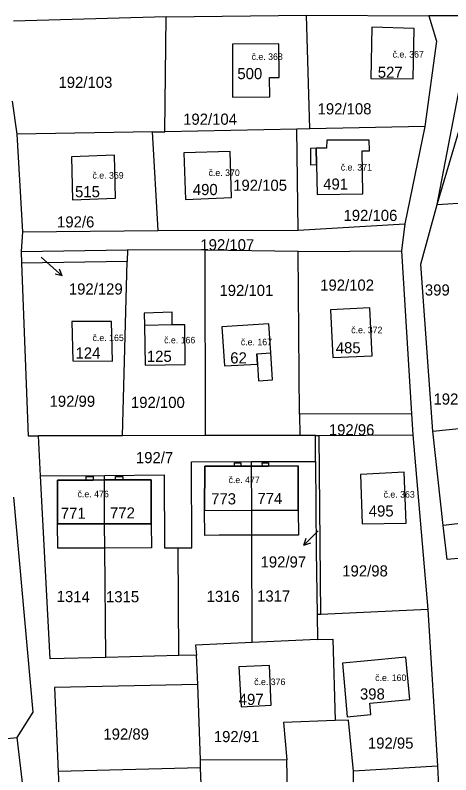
# Model space of a CAD drawing. Extents: x -887272 to -880188, y -1026687 to -1021896.
# Drawn here: x -882399.7 to -882333.3, y -1024170.3 to -1024054.5 of the extents above; entities that cross this region are included whole.
import ezdxf

# ---------------------------------------------------------------- set-up
doc = ezdxf.new("R2010")
doc.units = 0
for name, color, linetype in [('Definiční body', 7, 'Continuous'), ('Hranice parcel', 7, 'Continuous'), ('Parcelní čísla', 7, 'Continuous'), ('Polygon budovy', 7, 'Continuous'), ('Pop  PČ popisy', 7, 'Continuous'), ('Vnitřní kresba', 7, 'Continuous')]:
    doc.layers.add(name, color=color, linetype=linetype)

msp = doc.modelspace()

# ---------------------------------------------------------------- linework, layer by layer
at = {"layer": 'Hranice parcel'}
for p, q in [((-882376.66, -1024054.74), (-882399.93, -1024055.4)), ((-882376.88, -1024072.24), (-882376.66, -1024054.74)), ((-882376.66, -1024054.74), (-882355.26, -1024054.47)), ((-882355.26, -1024054.47), (-882336.63, -1024054.59)), ((-882354.76, -1024071.81), (-882355.26, -1024054.47)), ((-882330.93, -1024054.59), (-882336.63, -1024054.59)), ((-882400.17, -1024067.6), (-882399.46, -1024072.61)), ((-882335.35, -1024083.33), (-882331.18, -1024069.25)), ((-882378.73, -1024072.28), (-882399.46, -1024072.61)), ((-882378.73, -1024072.28), (-882376.88, -1024072.24)), ((-882377.91, -1024087.31), (-882378.73, -1024072.28)), ((-882356.76, -1024071.85), (-882376.88, -1024072.24)), ((-882354.76, -1024071.81), (-882356.76, -1024071.85)), ((-882356.55, -1024087.26), (-882356.76, -1024071.85)), ((-882337.23, -1024071.47), (-882354.76, -1024071.81)), ((-882337.23, -1024071.47), (-882340.25, -1024086.3)), ((-882399.46, -1024072.61), (-882398.59, -1024087.52)), ((-882335.35, -1024083.33), (-882328.64, -1024082.94)), ((-882356.55, -1024087.26), (-882340.25, -1024086.3)), ((-882340.25, -1024086.3), (-882340.76, -1024090.41)), ((-882398.59, -1024087.52), (-882398.79, -1024090.5)), ((-882398.59, -1024087.52), (-882377.91, -1024087.31)), ((-882377.91, -1024087.31), (-882356.55, -1024087.26)), ((-882398.79, -1024090.5), (-882382.57, -1024090.25)), ((-882398.79, -1024090.5), (-882398.72, -1024092.28)), ((-882382.57, -1024090.25), (-882382.62, -1024092.03)), ((-882370.74, -1024090.3), (-882382.57, -1024090.25)), ((-882370.69, -1024118.6), (-882370.74, -1024090.3)), ((-882356.54, -1024090.49), (-882370.74, -1024090.3)), ((-882356.54, -1024090.49), (-882340.76, -1024090.41)), ((-882356.32, -1024115.33), (-882356.54, -1024090.49)), ((-882340.76, -1024090.41), (-882339.24, -1024115.27)), ((-882382.62, -1024092.03), (-882398.72, -1024092.28)), ((-882383.34, -1024118.62), (-882382.62, -1024092.03)), ((-882339.24, -1024115.27), (-882356.32, -1024115.33)), ((-882356.32, -1024115.33), (-882356.29, -1024118.58)), ((-882339.24, -1024115.27), (-882339.04, -1024118.5)), ((-882336.02, -1024117.94), (-882325.37, -1024116.79)), ((-882383.34, -1024118.62), (-882396.14, -1024118.64)), ((-882395.82, -1024124.73), (-882396.14, -1024118.64)), ((-882370.69, -1024118.6), (-882383.34, -1024118.62)), ((-882356.29, -1024118.58), (-882370.69, -1024118.6)), ((-882353.89, -1024118.58), (-882356.29, -1024118.58)), ((-882353.87, -1024122.53), (-882353.89, -1024118.58)), ((-882353.89, -1024118.58), (-882353.31, -1024118.58)), ((-882353.31, -1024118.58), (-882339.04, -1024118.5)), ((-882353.07, -1024145.86), (-882353.31, -1024118.58)), ((-882339.04, -1024118.5), (-882336.77, -1024145.14)), ((-882334.41, -1024132.3), (-882336.02, -1024117.94)), ((-882372.79, -1024122.59), (-882363.66, -1024122.56)), ((-882363.66, -1024122.56), (-882353.87, -1024122.53)), ((-882363.66, -1024123.26), (-882363.66, -1024122.56)), ((-882395.82, -1024124.73), (-882386.09, -1024124.66)), ((-882394.36, -1024152.64), (-882395.82, -1024124.73)), ((-882386.09, -1024125.36), (-882386.09, -1024124.66)), ((-882307.23, -1024129.06), (-882334.41, -1024132.3)), ((-882363.55, -1024150.16), (-882363.6, -1024133.78)), ((-882385.89, -1024152.42), (-882386.04, -1024135.75)), ((-882374.74, -1024152.14), (-882374.83, -1024135.72)), ((-882336.77, -1024145.14), (-882353.07, -1024145.86)), ((-882336.77, -1024145.14), (-882335.28, -1024168.99)), ((-882353.07, -1024145.86), (-882353.66, -1024145.89)), ((-882353.66, -1024145.89), (-882353.61, -1024149.69)), ((-882353.61, -1024149.69), (-882363.55, -1024150.16)), ((-882385.89, -1024152.42), (-882394.36, -1024152.64)), ((-882374.74, -1024152.14), (-882385.89, -1024152.42)), ((-882372.02, -1024152.07), (-882374.74, -1024152.14)), ((-882371.86, -1024156.55), (-882372.02, -1024152.07)), ((-882371.86, -1024156.55), (-882393.69, -1024157.03)), ((-882393.69, -1024157.03), (-882393.14, -1024169.83)), ((-882371.45, -1024168.08), (-882371.86, -1024156.55)), ((-882416.18, -1024166.34), (-882399.41, -1024164.66)), ((-882398.41, -1024172.81), (-882399.41, -1024164.66)), ((-882358.24, -1024168.04), (-882371.45, -1024168.08)), ((-882371.41, -1024169.28), (-882371.45, -1024168.08)), ((-882358.04, -1024178.27), (-882358.24, -1024168.04)), ((-882371.41, -1024169.28), (-882393.14, -1024169.83)), ((-882370.74, -1024188.25), (-882371.41, -1024169.28)), ((-882335.28, -1024168.99), (-882348.11, -1024169.76)), ((-882347.76, -1024199.98), (-882348.11, -1024169.76)), ((-882335.28, -1024168.99), (-882334.7, -1024180.71))]:
    msp.add_line(p, q, dxfattribs=at)
for points in [[(-882336.63, -1024054.59), (-882335.46, -1024058.41), (-882337.23, -1024071.47)], [(-882339.02, -1024064.16), (-882338.84, -1024056.48), (-882345.3, -1024056.28), (-882345.46, -1024064.11), (-882339.02, -1024064.16)], [(-882366.57, -1024058.88), (-882366.57, -1024066.97), (-882360.88, -1024066.93), (-882360.89, -1024063.99), (-882359.44, -1024063.98), (-882359.47, -1024058.83), (-882366.57, -1024058.88)], [(-882335.35, -1024083.33), (-882331.89, -1024065.34), (-882329.46, -1024061.27)], [(-882345.63, -1024075.14), (-882345.69, -1024073.51), (-882352.16, -1024073.54), (-882352.21, -1024074.76), (-882353.78, -1024074.77), (-882354.67, -1024074.79), (-882354.63, -1024077.27), (-882353.73, -1024077.25), (-882353.65, -1024081.81), (-882346.65, -1024081.7), (-882346.75, -1024075.18), (-882345.63, -1024075.14)], [(-882391.09, -1024076.06), (-882390.93, -1024082.64), (-882384.37, -1024082.39), (-882384.53, -1024075.83), (-882391.09, -1024076.06)], [(-882366.72, -1024082.29), (-882366.89, -1024075.25), (-882373.99, -1024075.47), (-882373.74, -1024082.57), (-882366.72, -1024082.29)], [(-882336.02, -1024117.94), (-882337.81, -1024092.45), (-882335.35, -1024083.33)], [(-882398.72, -1024092.28), (-882397.69, -1024118.64), (-882396.14, -1024118.64)], [(-882351.61, -1024099.41), (-882351.25, -1024106.69), (-882345.26, -1024106.42), (-882345.58, -1024099.13), (-882351.61, -1024099.41)], [(-882373.8, -1024101.71), (-882375.74, -1024101.72), (-882375.76, -1024099.77), (-882380.01, -1024099.92), (-882379.98, -1024101.8), (-882379.88, -1024107.87), (-882373.78, -1024107.76), (-882373.8, -1024101.71)], [(-882384.98, -1024101.21), (-882391.03, -1024101.17), (-882390.91, -1024107.17), (-882384.86, -1024107.23), (-882384.98, -1024101.21)], [(-882360.43, -1024110.11), (-882360.72, -1024105.96), (-882361.02, -1024101.54), (-882368.16, -1024102.02), (-882367.76, -1024107.97), (-882362.73, -1024107.69), (-882362.56, -1024110.26), (-882360.43, -1024110.11)], [(-882374.83, -1024135.72), (-882372.77, -1024135.71), (-882372.79, -1024122.59)], [(-882363.6, -1024133.78), (-882368.56, -1024133.8), (-882370.77, -1024133.81), (-882370.83, -1024130), (-882370.78, -1024123.28), (-882366.24, -1024123.27), (-882366.25, -1024122.77), (-882365.29, -1024122.76), (-882365.29, -1024123.26), (-882363.66, -1024123.26)], [(-882363.66, -1024123.26), (-882361.98, -1024123.25), (-882362, -1024122.77), (-882361.07, -1024122.75), (-882361.07, -1024123.25), (-882356.53, -1024123.23), (-882356.51, -1024129.95), (-882356.49, -1024133.77), (-882363.6, -1024133.78)], [(-882363.6, -1024133.78), (-882363.62, -1024129.97), (-882363.66, -1024123.26)], [(-882353.87, -1024122.53), (-882353.79, -1024136.16), (-882353.66, -1024145.89)], [(-882386.09, -1024124.66), (-882376.96, -1024124.6), (-882376.9, -1024135.72), (-882374.83, -1024135.72)], [(-882340.36, -1024124.19), (-882347.03, -1024124.52), (-882346.75, -1024132.05), (-882340.04, -1024131.97), (-882340.36, -1024124.19)], [(-882386.04, -1024135.75), (-882393.2, -1024135.77), (-882393.22, -1024132.05), (-882393.22, -1024125.41), (-882388.88, -1024125.38), (-882388.88, -1024124.85), (-882387.81, -1024124.84), (-882387.79, -1024125.37), (-882386.09, -1024125.36)], [(-882386.09, -1024125.36), (-882384.38, -1024125.35), (-882384.37, -1024124.81), (-882383.28, -1024124.81), (-882383.28, -1024125.34), (-882378.96, -1024125.32), (-882378.93, -1024132.06), (-882378.9, -1024135.73), (-882386.04, -1024135.75)], [(-882386.04, -1024135.75), (-882386.08, -1024132.05), (-882386.09, -1024125.36)], [(-882399.41, -1024164.66), (-882396.97, -1024160.77), (-882399.92, -1024127.96)], [(-882326.6, -1024136.81), (-882333.83, -1024137.51), (-882334.41, -1024132.3)], [(-882353.61, -1024149.69), (-882351.25, -1024149.64), (-882350.89, -1024162.07)], [(-882363.55, -1024150.16), (-882372.18, -1024150.56), (-882372.02, -1024152.07)], [(-882345.46, -1024161.14), (-882345.61, -1024159.42), (-882339.52, -1024158.87), (-882340.1, -1024152.41), (-882346.49, -1024152.99), (-882349.79, -1024153.29), (-882349.05, -1024161.47), (-882345.46, -1024161.14)], [(-882360.93, -1024153.64), (-882365.56, -1024153.87), (-882365.25, -1024159.96), (-882360.66, -1024159.73), (-882360.93, -1024153.64)], [(-882350.89, -1024162.07), (-882358.75, -1024162.38), (-882358.24, -1024168.04)], [(-882348.11, -1024169.76), (-882348.87, -1024161.99), (-882350.89, -1024162.07)], [(-882393.14, -1024169.83), (-882392.82, -1024177.17), (-882390.17, -1024188.64)]]:
    msp.add_lwpolyline(points, dxfattribs=at)
at = {"layer": 'Polygon budovy'}
for points in [[(-882345.3, -1024056.28), (-882345.46, -1024064.11), (-882339.02, -1024064.16), (-882338.84, -1024056.48)], [(-882366.57, -1024066.97), (-882360.88, -1024066.93), (-882360.89, -1024063.99), (-882359.44, -1024063.98), (-882359.47, -1024058.83), (-882366.57, -1024058.88)], [(-882353.65, -1024081.81), (-882346.65, -1024081.7), (-882346.75, -1024075.18), (-882345.63, -1024075.14), (-882345.69, -1024073.51), (-882352.16, -1024073.54), (-882352.21, -1024074.76), (-882353.78, -1024074.77), (-882353.73, -1024077.25)], [(-882384.53, -1024075.83), (-882391.09, -1024076.06), (-882390.93, -1024082.64), (-882384.37, -1024082.39)], [(-882366.89, -1024075.25), (-882373.99, -1024075.47), (-882373.74, -1024082.57), (-882366.72, -1024082.29)], [(-882351.61, -1024099.41), (-882351.25, -1024106.69), (-882345.26, -1024106.42), (-882345.58, -1024099.13)], [(-882391.03, -1024101.17), (-882390.91, -1024107.17), (-882384.86, -1024107.23), (-882384.98, -1024101.21)], [(-882373.78, -1024107.76), (-882373.8, -1024101.71), (-882375.74, -1024101.72), (-882379.98, -1024101.8), (-882379.88, -1024107.87)], [(-882361.02, -1024101.54), (-882368.16, -1024102.02), (-882367.76, -1024107.97), (-882362.73, -1024107.69), (-882362.84, -1024106.11), (-882360.72, -1024105.96)], [(-882361.98, -1024123.25), (-882363.66, -1024123.26), (-882365.29, -1024123.26), (-882366.24, -1024123.27), (-882370.78, -1024123.28), (-882370.83, -1024130), (-882363.62, -1024129.97), (-882356.51, -1024129.95), (-882356.53, -1024123.23), (-882361.07, -1024123.25)], [(-882347.03, -1024124.52), (-882346.75, -1024132.05), (-882340.04, -1024131.97), (-882340.36, -1024124.19)], [(-882393.22, -1024125.41), (-882393.22, -1024132.05), (-882386.08, -1024132.05), (-882378.93, -1024132.06), (-882378.96, -1024125.32), (-882383.28, -1024125.34), (-882384.38, -1024125.35), (-882386.09, -1024125.36), (-882387.79, -1024125.37), (-882388.88, -1024125.38)], [(-882349.79, -1024153.29), (-882349.05, -1024161.47), (-882345.46, -1024161.14), (-882345.61, -1024159.42), (-882339.52, -1024158.87), (-882340.1, -1024152.41), (-882346.49, -1024152.99)], [(-882365.25, -1024159.96), (-882360.66, -1024159.73), (-882360.93, -1024153.64), (-882365.56, -1024153.87)]]:
    msp.add_lwpolyline(points, close=True, dxfattribs=at)
at = {"layer": 'Pop  PČ popisy'}
for p, q in [((-882395.72, -1024091.38), (-882394.75, -1024092.24)), ((-882394.75, -1024092.24), (-882392.52, -1024094.25)), ((-882392.52, -1024094.25), (-882392.93, -1024093.21)), ((-882392.52, -1024094.25), (-882393.6, -1024093.95)), ((-882353.55, -1024133.17), (-882355.67, -1024135.29)), ((-882353.48, -1024133.1), (-882353.55, -1024133.17)), ((-882355.67, -1024135.29), (-882355.32, -1024134.23)), ((-882355.67, -1024135.29), (-882354.61, -1024134.94))]:
    msp.add_line(p, q, dxfattribs=at)
at = {"layer": 'Vnitřní kresba'}
for p, q in [((-882353.73, -1024077.25), (-882353.78, -1024074.77)), ((-882375.74, -1024101.72), (-882379.98, -1024101.8)), ((-882362.84, -1024106.11), (-882360.72, -1024105.96)), ((-882362.84, -1024106.11), (-882362.73, -1024107.69)), ((-882366.24, -1024123.27), (-882365.29, -1024123.26)), ((-882361.98, -1024123.25), (-882361.07, -1024123.25)), ((-882388.88, -1024125.38), (-882387.79, -1024125.37)), ((-882384.38, -1024125.35), (-882383.28, -1024125.34)), ((-882370.83, -1024130), (-882363.62, -1024129.97)), ((-882363.62, -1024129.97), (-882356.51, -1024129.95)), ((-882386.08, -1024132.05), (-882393.22, -1024132.05)), ((-882378.93, -1024132.06), (-882386.08, -1024132.05))]:
    msp.add_line(p, q, dxfattribs=at)

# ---------------------------------------------------------------- texts
at = {"layer": 'Definiční body'}
for s, p in [('č.e. 368', (-882363.64, -1024061.3)), ('č.e. 367', (-882342.13, -1024060.94)), ('č.e. 371', (-882350.04, -1024078.17)), ('č.e. 370', (-882370.2, -1024079)), ('č.e. 369', (-882387.91, -1024079.4)), ('č.e. 372', (-882348.44, -1024102.98)), ('č.e. 165', (-882387.89, -1024104.18)), ('č.e. 166', (-882376.98, -1024104.53)), ('č.e. 167', (-882365.28, -1024104.82)), ('č.e. 477', (-882367.15, -1024125.84)), ('č.e. 476', (-882390.18, -1024128)), ('č.e. 363', (-882343.51, -1024128.06)), ('č.e. 376', (-882363.24, -1024156.65)), ('č.e. 160', (-882344.79, -1024156.03))]:
    msp.add_text(s, height=1, dxfattribs=at).set_placement(p)
at = {"layer": 'Parcelní čísla'}
for s, p in [('500', (-882365.81, -1024064.23)), ('527', (-882344.39, -1024064.02)), ('192/103', (-882393.09, -1024065.56)), ('192/108', (-882353.57, -1024069.6)), ('192/104', (-882374.08, -1024071.18)), ('491', (-882352.72, -1024081.08)), ('515', (-882390.56, -1024082.24)), ('490', (-882372.6, -1024081.91)), ('192/105', (-882366.45, -1024081.26)), ('192/106', (-882349.62, -1024085.86)), ('192/6', (-882393.31, -1024086.85)), ('192/107', (-882371.45, -1024090.34)), ('192/129', (-882391.51, -1024097.08)), ('192/101', (-882368.54, -1024097.3)), ('192/102', (-882353.18, -1024096.49)), ('399', (-882337.21, -1024097.23)), ('485', (-882350.8, -1024106.05)), ('124', (-882390.49, -1024106.85)), ('125', (-882379.61, -1024107.35)), ('62', (-882366.89, -1024107.59)), ('192/99', (-882394.45, -1024114.2)), ('192/100', (-882382.04, -1024114.38)), ('192/160', (-882335.9, -1024113.87)), ('192/96', (-882351.86, -1024118.56)), ('192/7', (-882381.28, -1024122.8)), ('773', (-882369.81, -1024129.09)), ('774', (-882362.75, -1024129.04)), ('495', (-882345.77, -1024130.94)), ('771', (-882392.73, -1024131.28)), ('772', (-882385.23, -1024131.23)), ('192/97', (-882362.27, -1024138.71)), ('192/98', (-882349.81, -1024140.08)), ('1315', (-882385.84, -1024144.02)), ('1316', (-882370.49, -1024143.96)), ('1317', (-882362.8, -1024143.91)), ('497', (-882365.6, -1024159.68)), ('398', (-882347.11, -1024158.85)), ('192/89', (-882386.24, -1024164.97)), ('192/91', (-882369.4, -1024165.35)), ('192/95', (-882345.9, -1024166.35))]:
    msp.add_text(s, height=1.7, dxfattribs=at).set_placement(p)
msp.add_text('1314', height=1.7, rotation=359, dxfattribs=at).set_placement((-882393.37, -1024143.96))

doc.saveas('drawing.dxf')
